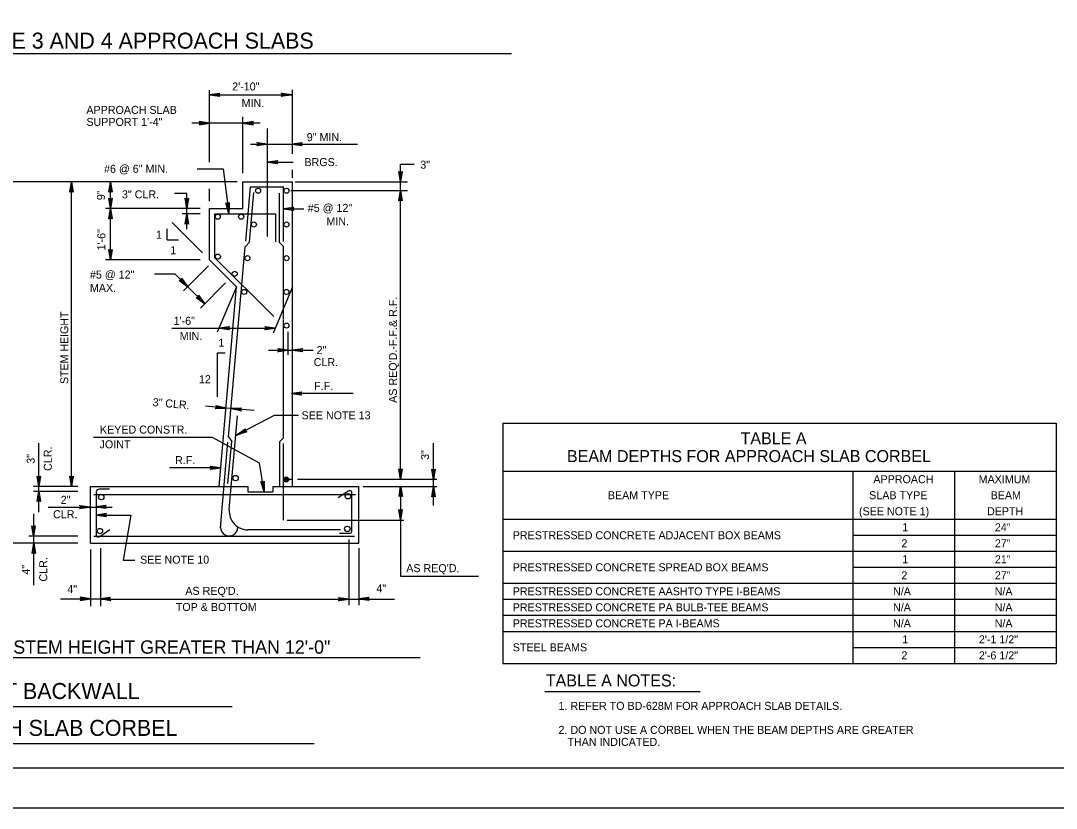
# Model space of a CAD drawing. Extents: x 235 to 2276, y 116 to 1308.
# Drawn here: x 807.5 to 1195.7, y 116.4 to 411.5 of the extents above; entities that cross this region are included whole.
import ezdxf

# ---------------------------------------------------------------- set-up
doc = ezdxf.new("R2010")
doc.units = 0
doc.layers.add('1', color=7, linetype='Continuous')
doc.layers.add('PLT-BNDY', color=7, linetype='Continuous')

msp = doc.modelspace()

# ---------------------------------------------------------------- linework, layer by layer
at = {"layer": '1'}
for p, q in [((627.1, 399.19), (991.42, 399.19)), ((878.32, 358.48), (878.32, 385.45)), ((909.41, 361.63), (909.41, 385.63)), ((878.32, 383.69), (909.41, 383.69)), ((878.32, 373.16), (871.73, 373.16)), ((890.74, 373.16), (878.32, 373.16)), ((890.74, 354.37), (890.74, 375.52)), ((897.34, 373.16), (890.74, 373.16)), ((900.08, 330.66), (900.08, 371.1)), ((893.65, 365.22), (900.08, 365.22)), ((900.08, 365.22), (933.82, 365.22)), ((900.08, 358.48), (909.61, 358.48)), ((949.9, 347.84), (949.9, 357.72)), ((949.9, 357.72), (955.03, 357.72)), ((873.73, 355.95), (883.41, 355.95)), ((883.41, 355.95), (885.56, 339.32)), ((909.41, 352.63), (909.41, 355.57)), ((888.68, 351.17), (803.33, 351.17)), ((826.61, 237.01), (826.61, 351.17)), ((841.23, 341.09), (841.23, 351.17)), ((890.74, 351.17), (909.41, 351.17)), ((890.74, 341.09), (890.74, 351.17)), ((909.41, 237.01), (909.41, 351.17)), ((910.41, 351.17), (952.55, 351.17)), ((869.81, 346.76), (865.12, 346.76)), ((869.81, 341.09), (869.81, 346.76)), ((878.32, 343.86), (878.32, 348.55)), ((891.89, 328.93), (893.7, 349.3)), ((893.27, 328.55), (894.93, 347.15)), ((893.7, 349.3), (905.99, 349.3)), ((904.58, 328.46), (904.58, 346.84)), ((905.99, 328.75), (905.99, 349.3)), ((908.8, 347.84), (952.55, 347.84)), ((949.9, 239.67), (949.9, 347.84)), ((874.77, 341.09), (839.28, 341.09)), ((841.23, 321.85), (841.23, 341.09)), ((874.77, 339.09), (868.1, 339.09)), ((869.81, 339.09), (869.81, 341.09)), ((869.81, 333.36), (869.81, 339.09)), ((878.32, 321.85), (878.32, 341.09)), ((878.32, 341.09), (890.74, 341.09)), ((880.32, 322.68), (880.32, 339.09)), ((880.32, 339.09), (903.18, 339.09)), ((903.18, 328.6), (903.18, 339.09)), ((905.99, 341.02), (913.63, 341.02)), ((875.62, 324.55), (864.26, 335.91)), ((862.41, 329.37), (862.41, 333.58)), ((862.41, 329.37), (866.63, 329.37)), ((885.36, 255.61), (891.7, 326.81)), ((891.7, 326.81), (893.27, 328.55)), ((905.99, 326.9), (904.58, 328.46)), ((905.99, 299.63), (905.99, 326.9)), ((902.37, 300.63), (880.32, 322.68)), ((874.77, 321.85), (839.28, 321.85)), ((877.96, 319.66), (868.6, 310.29)), ((888.41, 311.76), (878.32, 321.85)), ((865.47, 316.53), (857.74, 316.53)), ((870.15, 311.85), (865.47, 316.53)), ((876.54, 305.46), (870.15, 311.85)), ((884.35, 313.27), (874.91, 303.83)), ((888.41, 311.76), (881.23, 294.75)), ((881.93, 237.01), (888.41, 311.76)), ((909.41, 311.76), (902.1, 294.44)), ((905.99, 255.26), (905.99, 299.4)), ((864.12, 296.26), (881.86, 296.26)), ((881.86, 296.26), (902.87, 296.26)), ((907.79, 286.37), (907.79, 294.89)), ((900.37, 288.03), (907.79, 288.03)), ((907.79, 288.03), (909.41, 288.03)), ((909.41, 288.03), (917.21, 288.03)), ((881.32, 270.62), (881.32, 287.03)), ((881.32, 287.03), (884.14, 287.03)), ((909.11, 271.89), (932.08, 271.89)), ((884.27, 266.39), (876.8, 267.05)), ((895.05, 265.45), (884.48, 266.39)), ((885.72, 228.35), (888.84, 263.42)), ((902.55, 263.52), (888.45, 256.27)), ((911.61, 263.52), (902.55, 263.52)), ((988.23, 260.71), (988.23, 170.71)), ((988.23, 260.71), (1195.61, 260.71)), ((1195.61, 260.71), (1195.61, 170.71)), ((814.33, 237.01), (814.33, 253.16)), ((879.43, 255.29), (834.85, 255.29)), ((897.08, 245.76), (879.43, 255.29)), ((882.4, 221.54), (885.21, 253.57)), ((885.21, 238.11), (886.61, 253.89)), ((885.36, 255.61), (886.61, 253.89)), ((904.62, 253.89), (905.99, 255.26)), ((904.62, 237.01), (904.62, 253.89)), ((905.99, 224.36), (905.99, 253.03)), ((962.24, 239.67), (962.24, 253.16)), ((898.84, 234.98), (897.08, 245.76)), ((863.32, 244.04), (882.55, 244.04)), ((988.23, 242.71), (1195.61, 242.71)), ((1119.41, 242.71), (1119.41, 170.71)), ((1157.51, 242.71), (1157.51, 170.71)), ((828.94, 237.01), (812.35, 237.01)), ((814.33, 227.32), (814.33, 237.01)), ((833.65, 215.76), (833.65, 237.01)), ((833.65, 237.01), (892.71, 237.01)), ((892.71, 237.01), (892.71, 234.98)), ((902.08, 237.01), (934.27, 237.01)), ((902.08, 237.01), (902.08, 234.98)), ((908.33, 239.67), (909.58, 239.67)), ((911.25, 239.67), (963.49, 239.67)), ((934.27, 215.76), (934.27, 237.01)), ((935.9, 237.01), (963.49, 237.01)), ((949.9, 237.01), (949.9, 224.36)), ((962.22, 229.86), (962.22, 239.67)), ((828.94, 235.14), (812.35, 235.14)), ((834.9, 234.03), (933.02, 234.03)), ((835.83, 234.98), (835.83, 218.57)), ((840.83, 235.92), (837.08, 235.92)), ((892.71, 234.98), (902.08, 234.98)), ((930.21, 235.29), (926.46, 232.79)), ((931.61, 220.08), (931.61, 234.82)), ((817.81, 229.29), (833.65, 229.29)), ((833.65, 229.29), (841.83, 229.29)), ((812.4, 215.76), (812.4, 226.7)), ((835.83, 226.3), (848.79, 226.3)), ((848.79, 226.3), (845.89, 209.4)), ((907.4, 224.36), (943.02, 224.36)), ((943.02, 224.36), (951.15, 224.36)), ((949.9, 224.36), (949.9, 203.33)), ((988.23, 224.71), (1195.61, 224.71)), ((828.94, 218.42), (810.52, 218.42)), ((834.95, 218.42), (932.61, 218.42)), ((837.24, 218.26), (840.99, 220.92)), ((927.45, 220.73), (892.69, 220.73)), ((927.03, 219.45), (930.99, 219.45)), ((1119.41, 218.71), (1195.61, 218.71)), ((828.94, 215.76), (803.33, 215.76)), ((812.4, 200.07), (812.4, 215.76)), ((833.65, 215.76), (934.27, 215.76)), ((837.4, 213.89), (837.4, 192.17)), ((930.52, 217.17), (930.52, 192.48)), ((934.27, 213.89), (934.27, 192.48)), ((833.65, 213.42), (833.65, 192.17)), ((988.23, 212.71), (1195.61, 212.71)), ((845.89, 209.4), (850.26, 209.4)), ((1119.41, 206.71), (1195.61, 206.71)), ((949.9, 203.33), (979.15, 203.33)), ((988.23, 200.71), (1195.61, 200.71)), ((837.4, 194.82), (822.39, 194.82)), ((837.4, 194.82), (930.52, 194.82)), ((930.52, 194.82), (947.59, 194.82)), ((988.23, 194.71), (1195.61, 194.71)), ((988.23, 188.71), (1195.61, 188.71)), ((988.23, 182.71), (1195.61, 182.71)), ((1119.41, 176.71), (1195.61, 176.71)), ((801.95, 172.87), (957.24, 172.87)), ((988.23, 170.71), (1195.61, 170.71)), ((1003.96, 160.12), (1062.14, 160.12)), ((693.48, 154.61), (886.82, 154.61)), ((660.27, 140.7), (917.48, 140.7)), ((1405.42, 131.41), (619.42, 131.41))]:
    msp.add_line(p, q, dxfattribs=at)
for points in [[(882.07, 383.19), (881.94, 383.44), (878.32, 383.69), (882.07, 383.19), (882.19, 383.07), (878.32, 383.69), (881.94, 383.82), (882.07, 384.19), (878.32, 383.69), (882.19, 384.32), (882.07, 384.19)], [(905.36, 384.19), (905.49, 383.94), (909.11, 383.69), (905.36, 384.19), (905.11, 384.32), (909.11, 383.69), (905.49, 383.57), (905.36, 383.32), (909.11, 383.69), (905.11, 383.07), (905.36, 383.32)], [(874.57, 372.66), (874.69, 372.91), (878.32, 373.16), (874.57, 372.66), (874.44, 372.54), (878.32, 373.16), (874.69, 373.29), (874.57, 373.66), (878.32, 373.16), (874.44, 373.79), (874.57, 373.66)], [(894.49, 373.66), (894.36, 373.41), (890.74, 373.16), (894.49, 373.66), (894.74, 373.79), (890.74, 373.16), (894.36, 373.04), (894.49, 372.79), (890.74, 373.16), (894.74, 372.54), (894.49, 372.79)], [(896.33, 365.72), (896.45, 365.47), (900.08, 365.22), (896.33, 365.72), (896.08, 365.84), (900.08, 365.22), (896.45, 365.09), (896.33, 364.84), (900.08, 365.22), (896.08, 364.59), (896.33, 364.84)], [(912.86, 364.72), (912.74, 364.97), (909.11, 365.22), (912.86, 364.72), (912.99, 364.59), (909.11, 365.22), (912.74, 365.34), (912.86, 365.72), (909.11, 365.22), (912.99, 365.84), (912.86, 365.72)], [(903.83, 357.98), (903.7, 358.23), (900.08, 358.48), (903.83, 357.98), (903.95, 357.86), (900.08, 358.48), (903.7, 358.61), (903.83, 358.98), (900.08, 358.48), (903.95, 359.11), (903.83, 358.98)], [(950.4, 354.92), (950.15, 354.67), (949.9, 351.17), (950.4, 354.92), (950.52, 355.05), (949.9, 351.17), (949.77, 354.67), (949.52, 354.8), (949.9, 351.17), (949.27, 355.05), (949.52, 354.8)], [(826.11, 347.42), (826.36, 347.55), (826.61, 351.17), (826.11, 347.42), (825.99, 347.3), (826.61, 351.17), (826.74, 347.55), (827.11, 347.42), (826.61, 351.17), (827.24, 347.3), (827.11, 347.42)], [(840.73, 347.42), (840.98, 347.55), (841.23, 351.17), (840.73, 347.42), (840.61, 347.3), (841.23, 351.17), (841.36, 347.55), (841.73, 347.42), (841.23, 351.17), (841.86, 347.3), (841.73, 347.42)], [(949.4, 344.09), (949.65, 344.21), (949.9, 347.84), (949.4, 344.09), (949.27, 343.96), (949.9, 347.84), (950.02, 344.21), (950.4, 344.09), (949.9, 347.84), (950.52, 343.96), (950.4, 344.09)], [(841.73, 344.84), (841.48, 344.59), (841.23, 341.09), (841.73, 344.84), (841.86, 344.97), (841.23, 341.09), (841.11, 344.59), (840.73, 344.72), (841.23, 341.09), (840.61, 344.97), (840.73, 344.72)], [(870.31, 344.84), (870.06, 344.59), (869.81, 341.09), (870.31, 344.84), (870.44, 344.97), (869.81, 341.09), (869.69, 344.59), (869.31, 344.72), (869.81, 341.09), (869.19, 344.97), (869.31, 344.72)], [(885.61, 343.1), (885.37, 342.95), (885.56, 339.32), (885.61, 343.1), (885.7, 343.37), (885.56, 339.32), (885, 342.9), (884.74, 343), (885.56, 339.32), (884.46, 343.22), (884.74, 343)], [(909.74, 340.52), (909.61, 340.77), (905.99, 341.02), (909.74, 340.52), (909.86, 340.4), (905.99, 341.02), (909.61, 341.15), (909.74, 341.52), (905.99, 341.02), (909.86, 341.65), (909.74, 341.52)], [(840.73, 337.34), (840.98, 337.47), (841.23, 341.09), (840.73, 337.34), (840.61, 337.22), (841.23, 341.09), (841.36, 337.47), (841.73, 337.34), (841.23, 341.09), (841.86, 337.22), (841.73, 337.34)], [(869.31, 335.34), (869.56, 335.47), (869.81, 339.09), (869.31, 335.34), (869.19, 335.22), (869.81, 339.09), (869.94, 335.47), (870.31, 335.34), (869.81, 339.09), (870.44, 335.22), (870.31, 335.34)], [(841.73, 325.6), (841.48, 325.35), (841.23, 321.85), (841.73, 325.6), (841.86, 325.73), (841.23, 321.85), (841.11, 325.35), (840.73, 325.48), (841.23, 321.85), (840.61, 325.73), (840.73, 325.48)], [(867.81, 314.82), (867.82, 314.47), (870.15, 311.85), (867.81, 314.82), (867.81, 315), (870.15, 311.85), (867.55, 314.2), (867.2, 314.02), (870.15, 311.85), (866.94, 314.1), (867.2, 314.02)], [(874.2, 308.43), (874.2, 308.08), (876.54, 305.46), (874.2, 308.43), (874.2, 308.61), (876.54, 305.46), (873.94, 307.81), (873.59, 307.63), (876.54, 305.46), (873.32, 307.71), (873.59, 307.63)], [(885.61, 295.76), (885.49, 296.01), (881.86, 296.26), (885.61, 295.76), (885.74, 295.63), (881.86, 296.26), (885.49, 296.38), (885.61, 296.76), (881.86, 296.26), (885.74, 296.88), (885.61, 296.76)], [(899.12, 296.76), (899.37, 296.51), (902.87, 296.26), (899.12, 296.76), (898.99, 296.88), (902.87, 296.26), (899.37, 296.13), (899.24, 295.76), (902.87, 296.26), (898.99, 295.63), (899.24, 295.76)], [(904.04, 288.53), (904.29, 288.28), (907.79, 288.03), (904.04, 288.53), (903.91, 288.65), (907.79, 288.03), (904.29, 287.9), (904.16, 287.53), (907.79, 288.03), (903.91, 287.4), (904.16, 287.53)], [(913.16, 287.53), (913.04, 287.78), (909.41, 288.03), (913.16, 287.53), (913.29, 287.4), (909.41, 288.03), (913.04, 288.15), (913.16, 288.53), (909.41, 288.03), (913.29, 288.65), (913.16, 288.53)], [(912.83, 271.37), (912.71, 271.62), (909.08, 271.87), (912.83, 271.37), (912.96, 271.25), (909.08, 271.87), (912.71, 272), (912.83, 272.37), (909.08, 271.87), (912.96, 272.5), (912.83, 272.37)], [(880.79, 267.19), (880.91, 266.91), (884.51, 266.39), (880.79, 267.19), (880.61, 267.37), (884.51, 266.39), (880.88, 266.53), (880.72, 266.27), (884.51, 266.39), (880.5, 266.11), (880.72, 266.27)], [(890.05, 265.43), (889.94, 265.71), (886.33, 266.24), (890.05, 265.43), (890.23, 265.24), (886.33, 266.24), (889.97, 266.09), (890.13, 266.35), (886.33, 266.24), (890.35, 266.51), (890.13, 266.35)], [(892.04, 257.56), (891.79, 257.74), (888.45, 256.27), (892.04, 257.56), (892.28, 257.5), (888.45, 256.27), (891.61, 258.07), (891.61, 258.38), (888.45, 256.27), (891.71, 258.63), (891.61, 258.38)], [(878.69, 244.51), (878.94, 244.26), (882.44, 244.01), (878.69, 244.51), (878.57, 244.64), (882.44, 244.01), (878.94, 243.89), (878.82, 243.51), (882.44, 244.01), (878.57, 243.39), (878.82, 243.51)], [(814.83, 240.76), (814.58, 240.51), (814.33, 237.01), (814.83, 240.76), (814.95, 240.89), (814.33, 237.01), (814.2, 240.51), (813.83, 240.64), (814.33, 237.01), (813.7, 240.89), (813.83, 240.64)], [(827.11, 240.76), (826.86, 240.51), (826.61, 237.01), (827.11, 240.76), (827.24, 240.89), (826.61, 237.01), (826.49, 240.51), (826.11, 240.64), (826.61, 237.01), (825.99, 240.89), (826.11, 240.64)], [(950.36, 243.43), (950.11, 243.18), (949.86, 239.68), (950.36, 243.43), (950.48, 243.56), (949.86, 239.68), (949.73, 243.18), (949.36, 243.31), (949.86, 239.68), (949.23, 243.56), (949.36, 243.31)], [(962.72, 243.34), (962.47, 243.09), (962.22, 239.59), (962.72, 243.34), (962.84, 243.47), (962.22, 239.59), (962.09, 243.09), (961.72, 243.22), (962.22, 239.59), (961.59, 243.47), (961.72, 243.22)], [(898.7, 238.79), (898.45, 238.6), (898.84, 234.98), (898.7, 238.79), (898.83, 239), (898.84, 234.98), (898.08, 238.54), (897.79, 238.63), (898.84, 234.98), (897.58, 238.8), (897.79, 238.63)], [(949.44, 233.33), (949.69, 233.46), (949.94, 237.08), (949.44, 233.33), (949.32, 233.21), (949.94, 237.08), (950.07, 233.46), (950.44, 233.33), (949.94, 237.08), (950.57, 233.21), (950.44, 233.33)], [(961.74, 233.26), (961.99, 233.39), (962.24, 237.01), (961.74, 233.26), (961.61, 233.14), (962.24, 237.01), (962.36, 233.39), (962.74, 233.26), (962.24, 237.01), (962.86, 233.14), (962.74, 233.26)], [(813.86, 231.43), (814.11, 231.56), (814.36, 235.18), (813.86, 231.43), (813.73, 231.31), (814.36, 235.18), (814.48, 231.56), (814.86, 231.43), (814.36, 235.18), (814.98, 231.31), (814.86, 231.43)], [(829.87, 229.78), (830, 229.53), (833.62, 229.28), (829.87, 229.78), (829.62, 229.91), (833.62, 229.28), (830, 229.16), (829.87, 228.91), (833.62, 229.28), (829.62, 228.66), (829.87, 228.91)], [(839.42, 228.81), (839.29, 229.06), (835.67, 229.31), (839.42, 228.81), (839.54, 228.68), (835.67, 229.31), (839.29, 229.43), (839.42, 229.81), (835.67, 229.31), (839.54, 229.93), (839.42, 229.81)], [(839.58, 225.8), (839.46, 226.05), (835.83, 226.3), (839.58, 225.8), (839.71, 225.67), (835.83, 226.3), (839.46, 226.42), (839.58, 226.8), (835.83, 226.3), (839.71, 226.92), (839.58, 226.8)], [(950.39, 228.23), (950.14, 227.98), (949.89, 224.48), (950.39, 228.23), (950.51, 228.35), (949.89, 224.48), (949.76, 227.98), (949.39, 228.1), (949.89, 224.48), (949.26, 228.35), (949.39, 228.1)], [(812.88, 222.12), (812.63, 221.87), (812.38, 218.37), (812.88, 222.12), (813.01, 222.24), (812.38, 218.37), (812.26, 221.87), (811.88, 221.99), (812.38, 218.37), (811.76, 222.24), (811.88, 221.99)], [(811.91, 212.04), (812.16, 212.16), (812.41, 215.79), (811.91, 212.04), (811.78, 211.91), (812.41, 215.79), (812.53, 212.16), (812.91, 212.04), (812.41, 215.79), (813.03, 211.91), (812.91, 212.04)], [(829.92, 194.38), (830.05, 194.63), (833.67, 194.88), (829.92, 194.38), (829.8, 194.25), (833.67, 194.88), (830.05, 195), (829.92, 195.38), (833.67, 194.88), (829.8, 195.5), (829.92, 195.38)], [(841.11, 194.33), (840.98, 194.58), (837.36, 194.83), (841.11, 194.33), (841.23, 194.2), (837.36, 194.83), (840.98, 194.95), (841.11, 195.33), (837.36, 194.83), (841.23, 195.45), (841.11, 195.33)], [(926.72, 195.31), (926.97, 195.06), (930.47, 194.81), (926.72, 195.31), (926.59, 195.44), (930.47, 194.81), (926.97, 194.69), (926.84, 194.31), (930.47, 194.81), (926.59, 194.19), (926.84, 194.31)], [(938.05, 194.34), (937.93, 194.59), (934.3, 194.84), (938.05, 194.34), (938.18, 194.22), (934.3, 194.84), (937.93, 194.97), (938.05, 195.34), (934.3, 194.84), (938.18, 195.47), (938.05, 195.34)]]:
    msp.add_lwpolyline(points, dxfattribs=at)
for centre, radius in [((896.49, 347.78), 0.954), ((907.13, 347.78), 0.954), ((881.37, 338.06), 0.954), ((890.17, 338.06), 0.954), ((894.93, 335.15), 0.954), ((907.13, 335.15), 0.954), ((881.41, 323.13), 0.954), ((892.51, 322.52), 0.954), ((907.13, 322.52), 0.954), ((887.73, 316.67), 0.954), ((891.31, 309.88), 0.954), ((907.13, 309.88), 0.954), ((907.13, 297.25), 0.954), ((888.08, 240.12), 1.01), ((907, 239.59), 0.954), ((907, 239.59), 0.681), ((907, 239.59), 0.372), ((907, 239.59), 0.188), ((907, 239.59), 0.0805), ((837.72, 232.99), 1.01), ((930.2, 233.33), 1.01), ((837.21, 220.28), 1.01), ((929.96, 221.1), 1.01)]:
    msp.add_circle(centre, radius, dxfattribs=at)
for centre, radius, start, end in [((892.69, 227.73), 7, 174.9079, 270), ((885.68, 221.66), 3.22, 180, 0), ((930.99, 220.08), 0.625, 270, 360)]:
    msp.add_arc(centre, radius, start, end, dxfattribs=at)
for centre, major_axis, ratio, start_param, end_param in [((837.1, 235.06), (-1.3, 0), 0.697544, 4.712389, 6.283185), ((930.86, 234.9), (-0.812, 0), 0.632693, 3.141593, 5.497787), ((836.61, 218.62), (0.812, 0), 0.697544, 3.141593, 5.497787)]:
    msp.add_ellipse(centre, major_axis=major_axis, ratio=ratio, start_param=start_param, end_param=end_param, dxfattribs=at)
at = {"layer": 'PLT-BNDY'}
msp.add_lwpolyline([(579.42, 710.41), (1420.42, 710.41), (1420.42, 116.41), (579.42, 116.41)], close=True, dxfattribs=at)

# ---------------------------------------------------------------- texts
at = {"layer": '1'}
for s, height, p in [('TYPICAL SECTION WITH BACKWALL FOR TYPE 3 AND 4 APPROACH SLABS', 6, (627.11, 401.03)), ('2\'-10"', 3.003, (886.79, 385.36)), ('MIN.', 3, (890.33, 379.13)), ('APPROACH SLAB', 3, (832.15, 376.58)), ('SUPPORT 1\'-4"', 3, (832.15, 372.08)), ('9" MIN.', 3.003, (914.75, 366.37)), ('#6 @ 6" MIN.', 3, (838.77, 354.51)), ('  BRGS.', 3, (911.64, 357.02)), ('3"', 3.003, (957.29, 356.05)), ('3" CLR.', 3.003, (845.48, 344.93)), ('#5 @ 12"', 3, (915.12, 339.87)), ('MIN.', 3, (922.11, 334.87)), ('1 ', 3, (858.23, 329.78)), ('1 ', 3, (863.61, 324)), ('#5 @ 12"', 3, (833.49, 314.88)), ('MAX.', 3, (833.49, 309.88)), ('1\'-6"', 3.003, (864.84, 297.55)), ('MIN.', 3, (867.13, 291.86)), ('1 ', 3, (881.63, 289.38)), (' 2"', 3, (917.33, 286.58)), ('CLR.', 3, (917.33, 282.08)), ('12', 3.003, (874.33, 275.68)), ('F.F.', 3, (917.52, 273.19)), ('SEE NOTE 13', 3, (912.8, 262.16)), ('KEYED CONSTR.', 3, (837.23, 256.8)), ('TABLE A', 4.5, (1077.32, 252.79)), ('JOINT', 3, (837.09, 251.28)), ('BEAM DEPTHS FOR APPROACH SLAB CORBEL', 4.5, (1012.26, 246.12)), ('R.F.', 3, (865.39, 245.38)), ('APPROACH', 3, (1127.11, 238.21)), ('MAXIMUM', 3, (1166.56, 238.21)), ('2"', 3.003, (822.53, 230.48)), ('BEAM TYPE', 3, (1027.6, 232.21)), ('SLAB TYPE', 3, (1125.54, 232.21)), ('BEAM', 3, (1171.06, 232.21)), ('(SEE NOTE 1)', 3, (1121.72, 226.2)), ('DEPTH', 3, (1169.71, 226.2)), ('CLR.', 3, (819.68, 225.09)), ('1', 3, (1137.95, 220.21)), ('24"', 3, (1172.65, 220.21)), ('PRESTRESSED CONCRETE ADJACENT BOX BEAMS', 3, (991.95, 217.21)), ('2', 3, (1137.61, 214.21)), ('27"', 3, (1172.65, 214.21)), ('SEE NOTE 10', 3, (852.29, 208.07)), ('1', 3, (1137.95, 208.21)), ('21"', 3, (1172.65, 208.21)), ("AS REQ'D.", 3, (952.04, 204.88)), ('PRESTRESSED CONCRETE SPREAD BOX BEAMS', 3, (991.95, 205.21)), ('2', 3, (1137.61, 202.21)), ('27"', 3, (1172.65, 202.21)), ('4"', 3.003, (825, 197.02)), ("AS REQ'D.", 3, (869.25, 196.38)), ('4"', 3.003, (940.83, 197.3)), ('PRESTRESSED CONCRETE AASHTO TYPE I-BEAMS', 3, (991.95, 196.21)), ('N/A', 3, (1134.48, 196.21)), ('N/A', 3, (1172.58, 196.21)), ('TOP & BOTTOM', 3, (865.66, 190.34)), ('PRESTRESSED CONCRETE PA BULB-TEE BEAMS', 3, (991.95, 190.21)), ('N/A', 3, (1134.48, 190.21)), ('N/A', 3, (1172.58, 190.21)), ('PRESTRESSED CONCRETE PA I-BEAMS', 3, (991.95, 184.21)), ('N/A', 3, (1134.48, 184.21)), ('N/A', 3, (1172.58, 184.21)), ('STEM HEIGHT GREATER THAN 12\'-0"', 5, (804.77, 174.33)), ('1', 3, (1137.95, 178.21)), ('2\'-1 1/2"', 3, (1166.65, 178.21)), ('STEEL BEAMS', 3, (991.95, 175.21)), ('2', 3, (1137.61, 172.21)), ('2\'-6 1/2"', 3, (1166.65, 172.21)), ('TABLE A NOTES:', 4.5, (1004.34, 162.06)), ('1. REFER TO BD-628M FOR APPROACH SLAB DETAILS.', 3, (1009.1, 153.29)), ('FOR TYPE 1 AND TYPE 2 APPROACH SLAB CORBEL', 6, (665.17, 143.54)), ('2. DO NOT USE A CORBEL WHEN THE BEAM DEPTHS ARE GREATER', 3, (1009.1, 144.29)), ('   THAN INDICATED.', 3, (1009.1, 139.79))]:
    msp.add_text(s, height=height, dxfattribs=at).set_placement(p)
for s, height, rotation, p in [('9"', 3, 90, (839.12, 344.27)), ('1\'-6"', 3, 90, (839.26, 325.43)), ("AS REQ'D.-F.F.& R.F.", 3, 90, (948.52, 268.32)), ('STEM HEIGHT', 2.97, 90, (825.36, 275.38)), ('3" CLR.', 3, 354.9865, (856.86, 267.14)), ('3"', 3, 90, (812.8, 245.5)), ('CLR.', 3, 90, (819.18, 242.82)), ('3"', 3, 90, (960.57, 246.93)), ('CLR.', 3, 90, (817.48, 201.37)), ('4"', 3, 90, (811.01, 203.95)), ('TYPICAL SECTION WITHOUT BACKWALL', 6, 360, (695.17, 157.36))]:
    msp.add_text(s, height=height, rotation=rotation, dxfattribs=at).set_placement(p)

doc.saveas('drawing.dxf')
